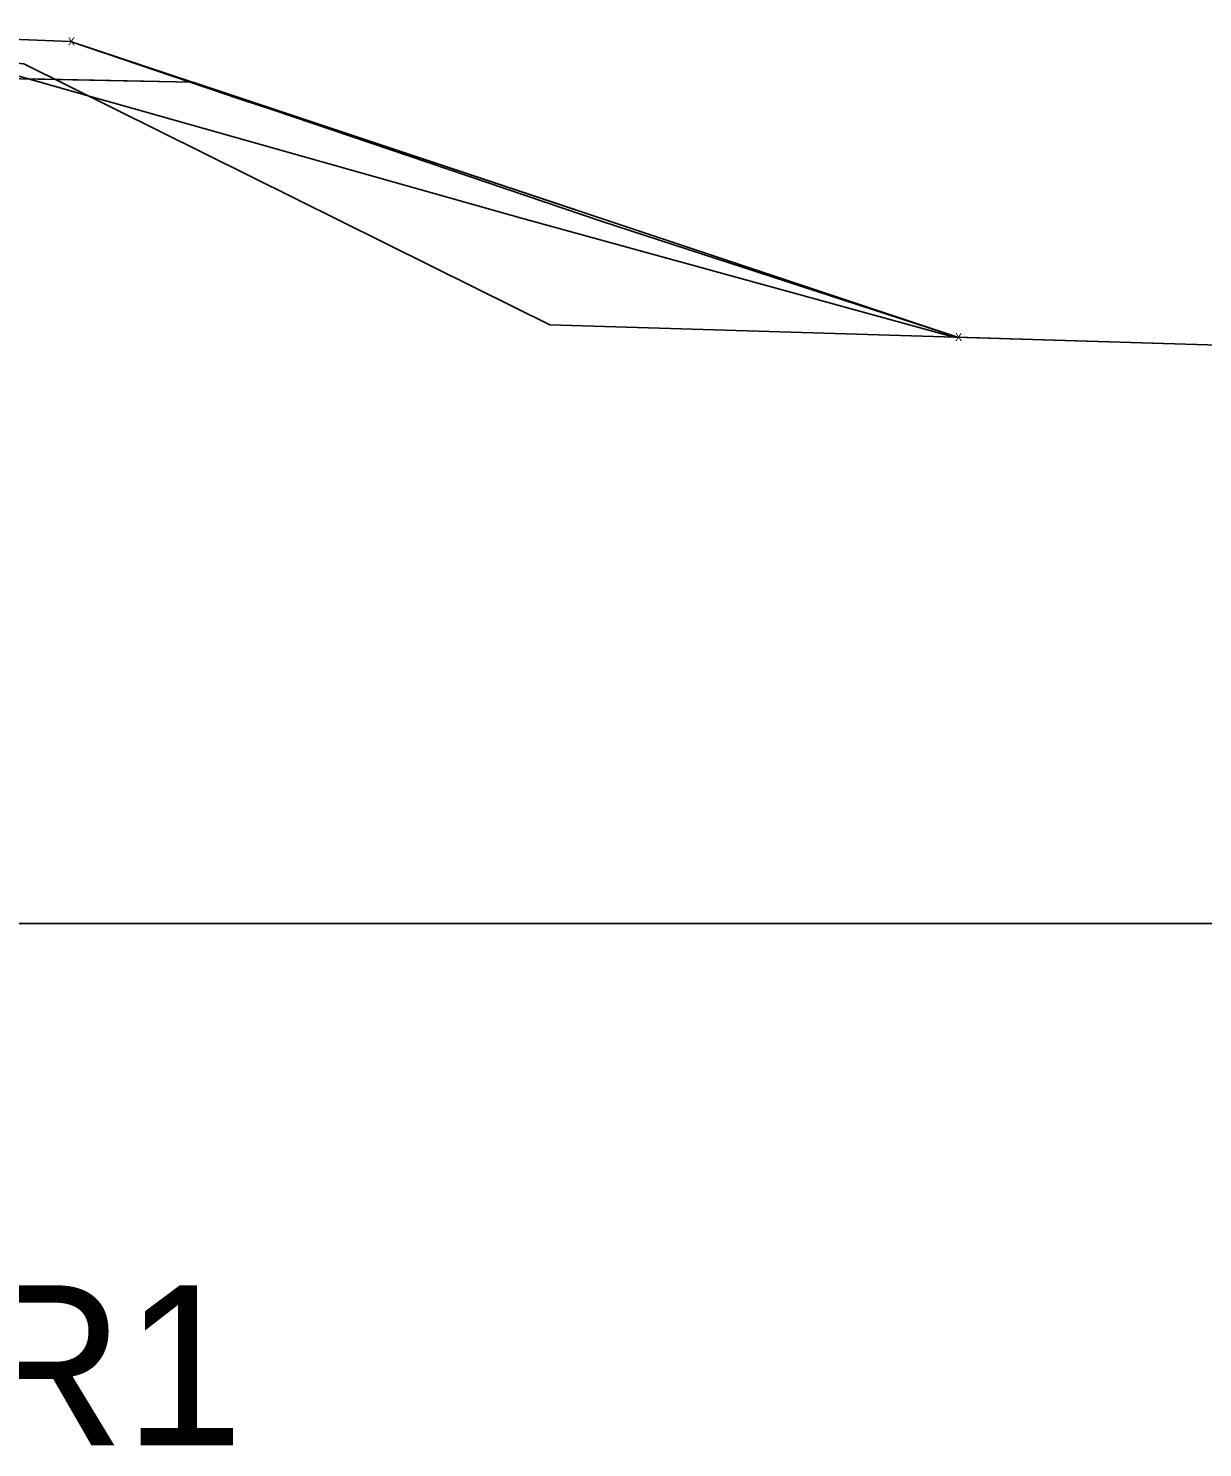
# Model space of a CAD drawing. Extents: x -26 to 303, y -16 to 6048.
# Drawn here: x 166.12 to 201.34, y 1984.28 to 2026.85 of the extents above; entities that cross this region are included whole.
import ezdxf

# ---------------------------------------------------------------- set-up
doc = ezdxf.new("R2010")
doc.units = 0
for name, color, linetype in [('Draft_XS_Text', 7, 'Continuous'), ('DTM_P_FINISHED_GRADE2', 7, 'Continuous'), ('DTM_TEMP_DROP', 7, 'Continuous'), ('DTM_X_GROUND', 7, 'Continuous'), ('XS_CELL', 7, 'Continuous'), ('XS_M_SHAPES_EARTHWORK', 7, 'Continuous'), ('XS_P_GROUND', 7, 'Continuous'), ('XS_P_SHOULDER', 7, 'Continuous'), ('XS_P_SUBGRADE_GRANULAR', 7, 'Continuous')]:
    doc.layers.add(name, color=color, linetype=linetype)

msp = doc.modelspace()

# ---------------------------------------------------------------- linework, layer by layer
at = {"layer": 'DTM_P_FINISHED_GRADE2'}
msp.add_lwpolyline([(103.19, 2016.726), (103.428, 2016.731), (131.918, 2026.302), (137.918, 2026.542), (139.919, 2026.593), (150, 2026.848), (159.298, 2026.726), (161.298, 2026.699), (167.381, 2026.456), (172.47, 2024.727), (173.481, 2024.391), (183.325, 2021.057), (193.989, 2017.587)], dxfattribs=at)
at = {"layer": 'DTM_X_GROUND'}
for points in [[(97.923, 2016.532), (101.4, 2016.662), (103.19, 2016.726), (103.346, 2016.729), (103.428, 2016.731), (129.878, 2024.228), (131.195, 2024.599), (137.918, 2026.542), (137.918, 2026.542), (139.919, 2026.593), (139.919, 2026.593), (150, 2026.848), (159.298, 2026.726), (159.298, 2026.726), (161.298, 2026.699), (161.298, 2026.699), (167.56, 2024.923), (168.261, 2024.728), (168.802, 2024.578), (180.91, 2021.154), (193.883, 2017.59), (193.989, 2017.587), (196.896, 2017.498), (203.123, 2017.307)], [(97.923, 2016.539), (106.131, 2016.831), (113.416, 2017.072), (115.411, 2017.161), (120.359, 2019.255), (137.083, 2025.752), (137.918, 2025.876), (146.352, 2026.125), (149.92, 2026.223), (153.19, 2026.22), (161.298, 2026.224), (163.765, 2025.996), (165.977, 2025.789), (179.536, 2019.058), (181.755, 2017.958), (203.123, 2017.309)]]:
    msp.add_lwpolyline(points, dxfattribs=at)
at = {"layer": 'XS_CELL'}
msp.add_line((150, 2000), (300, 2000), dxfattribs=at)
at = {"layer": 'XS_M_SHAPES_EARTHWORK'}
msp.add_lwpolyline([(166.118, 2025.332), (167.56, 2024.923), (168.261, 2024.728), (168.802, 2024.578), (180.91, 2021.154), (193.883, 2017.59), (193.989, 2017.587), (171.048, 2025.234)], close=True, dxfattribs=at)
at = {"layer": 'XS_P_GROUND'}
msp.add_lwpolyline([(193.989, 2017.587), (193.989, 2017.587), (167.381, 2026.456)], dxfattribs=at)
at = {"layer": 'XS_P_SHOULDER'}
msp.add_lwpolyline([(161.298, 2026.699), (167.381, 2026.456)], dxfattribs=at)
at = {"layer": 'XS_P_SUBGRADE_GRANULAR'}
msp.add_lwpolyline([(161.298, 2025.429), (163.298, 2025.389), (171.048, 2025.234)], dxfattribs=at)

# ---------------------------------------------------------------- texts
at = {"layer": 'Draft_XS_Text'}
msp.add_text('Sta. 164+50.0000 R1', height=4.8, dxfattribs=at).set_placement((111.716, 1984.35))
at = {"layer": 'DTM_TEMP_DROP'}
msp.add_text('X', height=0.24, dxfattribs=at).set_placement((193.911, 2017.467))
at = {"layer": 'XS_P_GROUND'}
msp.add_text('X', height=0.24, dxfattribs=at).set_placement((167.302, 2026.336))
at = {"layer": 'XS_P_SUBGRADE_GRANULAR'}
msp.add_text('X', height=0.24, dxfattribs=at).set_placement((193.911, 2017.467))

doc.saveas('drawing.dxf')
